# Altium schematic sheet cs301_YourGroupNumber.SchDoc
size A4
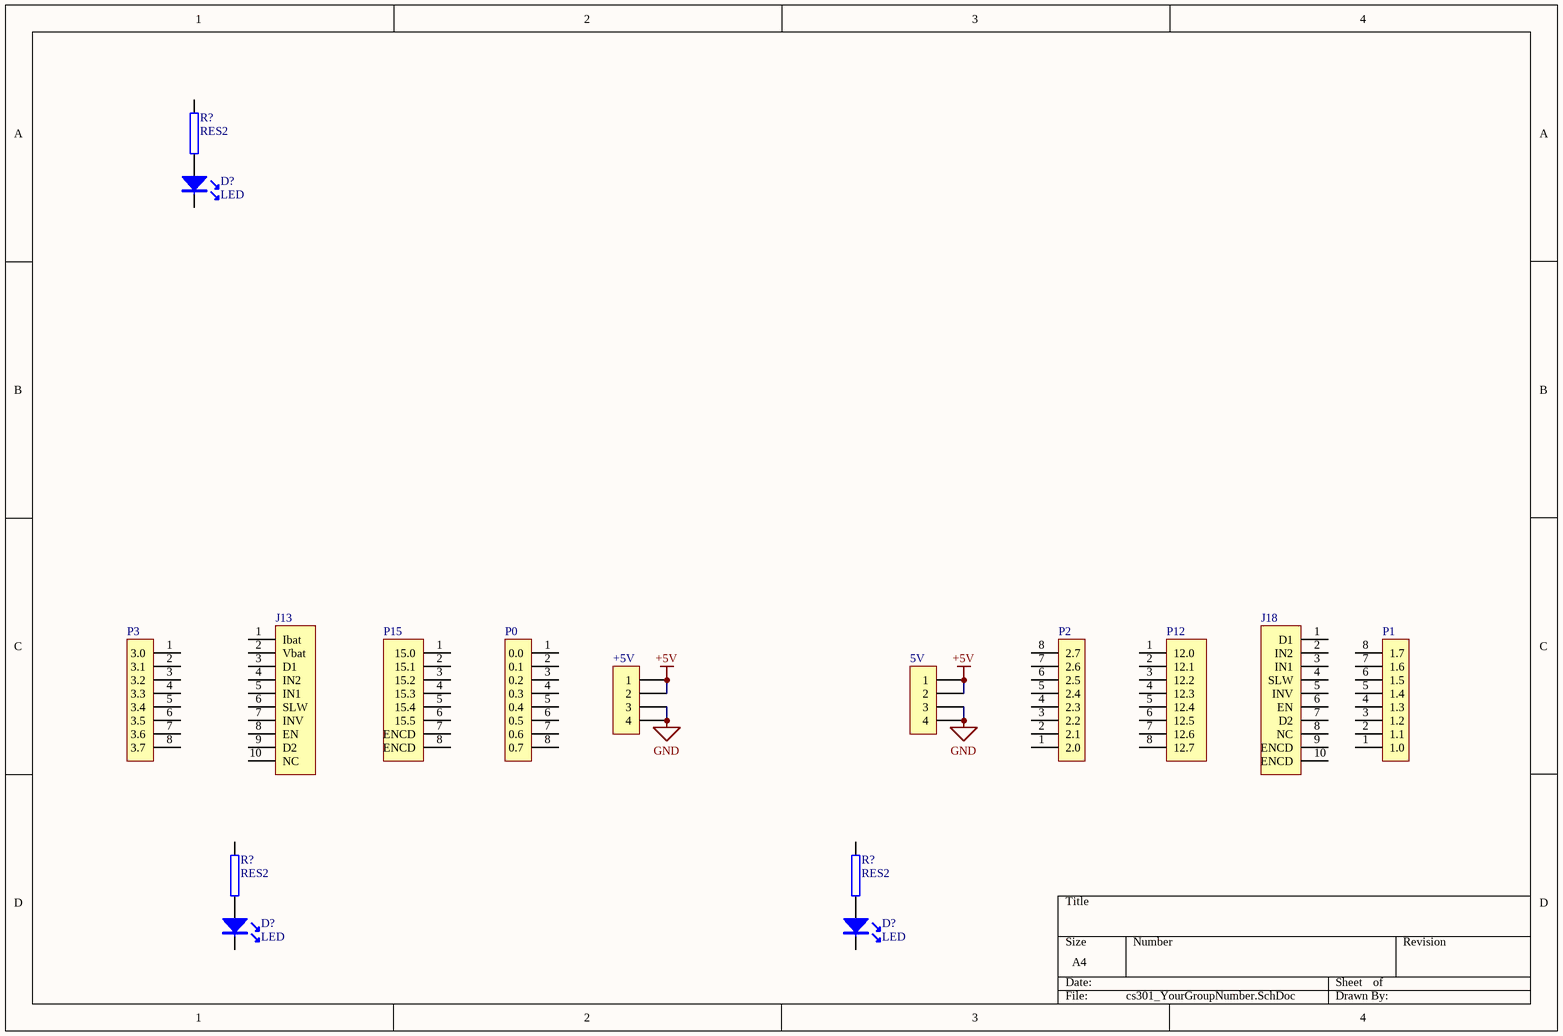
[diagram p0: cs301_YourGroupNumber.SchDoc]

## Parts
(Parts that share a designator on the sheet are numbered #1, #2 ... from top to bottom, then left to right.)
5V  5V  [IDC4]  (value not drawn)
+5V  5V  [IDC4]  (value not drawn)
D?#1  LED  [LED0.1/5MM]
D?#2  LED  [LED0.1/5MM]
D?#3  LED  [LED0.1/5MM]
J13  CON10  [idc10]  (value not drawn)
J18  CON10  [IDC10]  (value not drawn)
P0  P0  [idc8]  (value not drawn)
P1  P1  [idc8]  (value not drawn)
P2  P2  [idc8]  (value not drawn)
P3  P3  [idc8]  (value not drawn)
P12  P12  [idc8]  (value not drawn)
P15  P15  [idc8]  (value not drawn)
R?#1  RES2  [AXIAL0.4]
R?#2  RES2  [AXIAL0.4]
R?#3  RES2  [AXIAL0.4]

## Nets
+5V: 5V.1 5V.2 +5V.1 +5V.2
GND: 5V.3 5V.4 +5V.3 +5V.4
NetD?#1_A: D?#1.A R?#1.1
NetD?#2_A: D?#2.A R?#3.1
NetD?#3_A: D?#3.A R?#2.2

Not connected (* = marked no-connect by the designer): D?#1 K(2); D?#2 K(2); D?#3 K(2); J13 1(Ibat) 2(Vbat) 3(D1) 4(IN2) 5(IN1) 6(SLW) 7(INV) 8(EN) 9(D2) 10(NC); J18 1(D1) 2(IN2) 3(IN1) 4(SLW) 5(INV) 6(EN) 7(D2) 8(NC) 9(ENCD) 10(ENCD); P0 1(0.0) 2(0.1) 3(0.2) 4(0.3) 5(0.4) 6(0.5) 7(0.6) 8(0.7); P1 1(1.0) 2(1.1) 3(1.2) 4(1.3) 5(1.4) 6(1.5) 7(1.6) 8(1.7); P2 1(2.0) 2(2.1) 3(2.2) 4(2.3) 5(2.4) 6(2.5) 7(2.6) 8(2.7); P3 1(3.0) 2(3.1) 3(3.2) 4(3.3) 5(3.4) 6(3.5) 7(3.6) 8(3.7); P12 1(12.0) 2(12.1) 3(12.2) 4(12.3) 5(12.4) 6(12.5) 7(12.6) 8(12.7); P15 1(15.0) 2(15.1) 3(15.2) 4(15.3) 5(15.4) 6(15.5) 7(ENCD) 8(ENCD); R?#1 2; R?#2 1; R?#3 2

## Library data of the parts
5V +5V = CON4: Connector
J13 J18 = CON10: Connector
P0-P3 = CON8: Connector
P12 P15 = CON8_1: Connector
